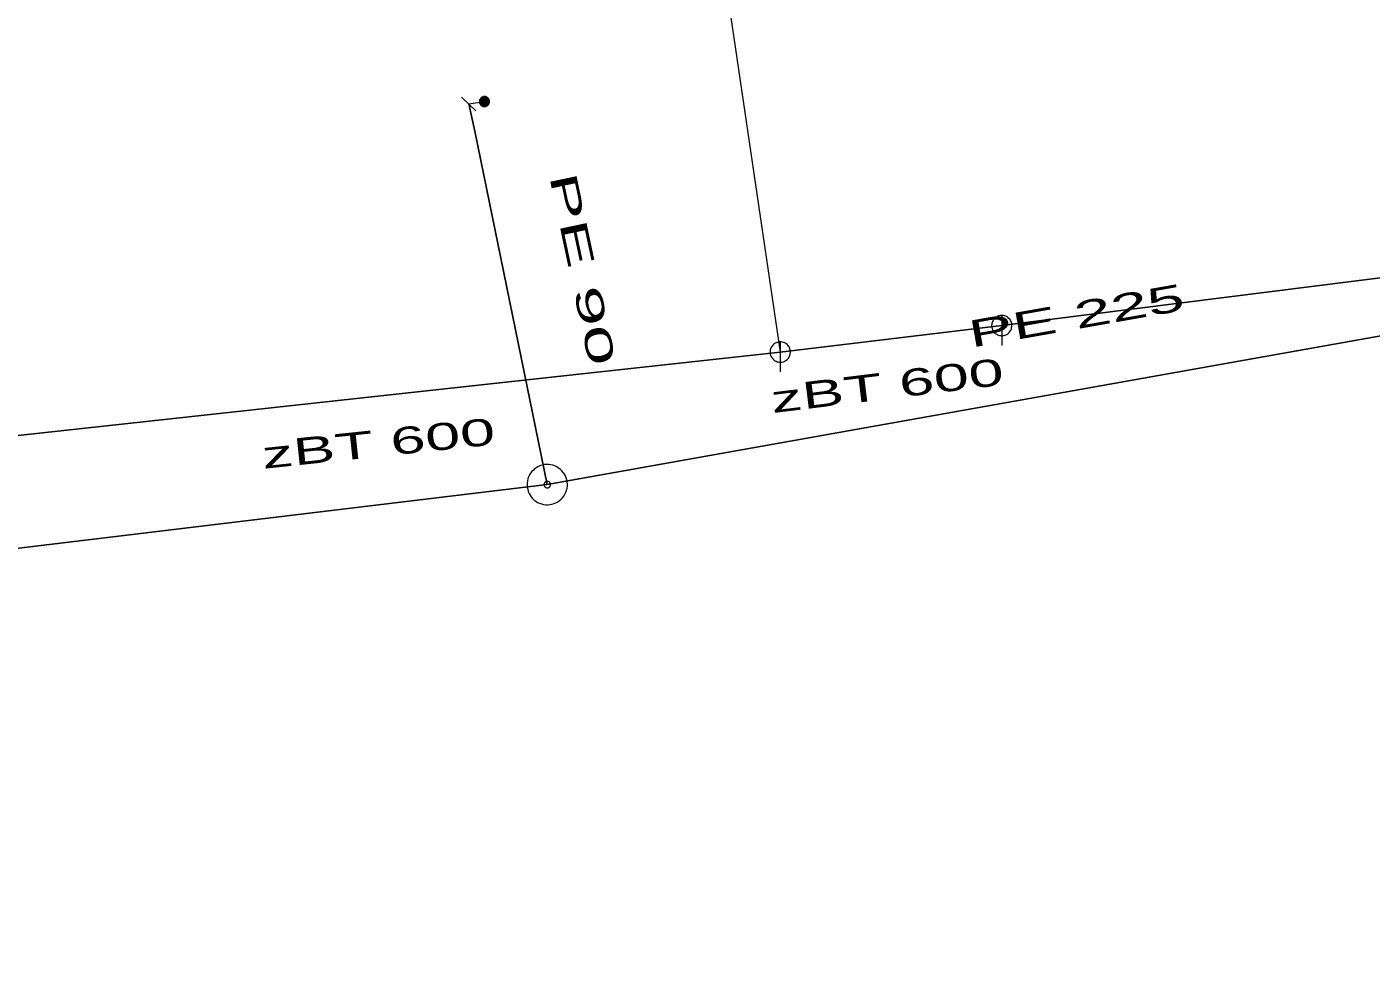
# Model space of a CAD drawing. Extents: x -687468 to -685917, y -974192 to -973456.
# Drawn here: x -686636.37 to -686603.02, y -973637.07 to -973613.79 of the extents above; entities that cross this region are included whole.
import ezdxf
from ezdxf.enums import TextEntityAlignment as Align

# ---------------------------------------------------------------- set-up
doc = ezdxf.new("R2010")
doc.units = 0
doc.header["$LTSCALE"] = 0.27
for name, color, linetype, lineweight in [('1', 7, 'Continuous', 13), ('11', 7, 'Continuous', 13), ('14', 7, 'Continuous', 25), ('17', 7, 'Continuous', 25), ('22', 7, 'Continuous', 13), ('34', 7, 'Continuous', 13), ('47', 7, 'Continuous', 13), ('9', 7, 'Continuous', 13)]:
    doc.layers.add(name, color=color, linetype=linetype, lineweight=lineweight)

msp = doc.modelspace()

# ---------------------------------------------------------------- linework, layer by layer
at = {"layer": '11'}
msp.add_lwpolyline([(-686607.101, -973609.27), (-686619.328, -973610.691), (-686617.682, -973621.851)], dxfattribs=at)
at = {"layer": '14', "lineweight": 13}
msp.add_line((-686625.41, -973615.7), (-686625.019, -973615.64), dxfattribs=at)
at = {"layer": '14'}
for p, q in [((-686587.336, -973618.056), (-686612.187, -973621.194)), ((-686612.187, -973621.194), (-686617.682, -973621.851)), ((-686617.682, -973621.851), (-686637.412, -973624.013))]:
    msp.add_line(p, q, dxfattribs=at)
at = {"layer": '17'}
for p, q in [((-686596.546, -973620.333), (-686623.461, -973625.138)), ((-686623.461, -973625.138), (-686722.815, -973637.075))]:
    msp.add_line(p, q, dxfattribs=at)
msp.add_lwpolyline([(-686623.461, -973625.138), (-686625.255, -973616.375), (-686625.41, -973615.7)], dxfattribs=at)
at = {"layer": '22'}
for p, q in [((-686612.186, -973620.942), (-686612.187, -973621.686)), ((-686617.681, -973621.599), (-686617.682, -973622.343))]:
    msp.add_line(p, q, dxfattribs=at)
for points in [[(-686611.935, -973621.194), (-686611.936, -973621.168), (-686611.94, -973621.142), (-686611.946, -973621.116), (-686611.956, -973621.092), (-686611.968, -973621.068), (-686611.982, -973621.046), (-686611.999, -973621.025), (-686612.017, -973621.007), (-686612.038, -973620.99), (-686612.06, -973620.976), (-686612.084, -973620.964), (-686612.108, -973620.954), (-686612.134, -973620.948), (-686612.16, -973620.944), (-686612.186, -973620.942), (-686612.212, -973620.943), (-686612.238, -973620.947), (-686612.264, -973620.953), (-686612.289, -973620.963), (-686612.312, -973620.975), (-686612.334, -973620.989), (-686612.355, -973621.006), (-686612.373, -973621.024), (-686612.39, -973621.045), (-686612.404, -973621.067), (-686612.416, -973621.091), (-686612.426, -973621.115), (-686612.433, -973621.141), (-686612.437, -973621.167), (-686612.439, -973621.193), (-686612.438, -973621.219), (-686612.434, -973621.245), (-686612.427, -973621.271), (-686612.417, -973621.296), (-686612.405, -973621.319), (-686612.391, -973621.341), (-686612.374, -973621.362), (-686612.356, -973621.38), (-686612.335, -973621.397), (-686612.313, -973621.411), (-686612.29, -973621.423), (-686612.265, -973621.433), (-686612.239, -973621.44), (-686612.213, -973621.444), (-686612.187, -973621.446), (-686612.161, -973621.445), (-686612.135, -973621.441), (-686612.109, -973621.434), (-686612.085, -973621.424), (-686612.061, -973621.412), (-686612.039, -973621.398), (-686612.018, -973621.381), (-686612, -973621.363), (-686611.983, -973621.342), (-686611.969, -973621.32), (-686611.957, -973621.297), (-686611.947, -973621.272), (-686611.941, -973621.246), (-686611.937, -973621.22)], [(-686617.43, -973621.851), (-686617.431, -973621.825), (-686617.435, -973621.799), (-686617.441, -973621.773), (-686617.451, -973621.749), (-686617.463, -973621.725), (-686617.477, -973621.703), (-686617.494, -973621.682), (-686617.512, -973621.664), (-686617.533, -973621.647), (-686617.555, -973621.633), (-686617.579, -973621.621), (-686617.603, -973621.611), (-686617.629, -973621.605), (-686617.655, -973621.601), (-686617.681, -973621.599), (-686617.707, -973621.6), (-686617.733, -973621.604), (-686617.759, -973621.61), (-686617.784, -973621.62), (-686617.807, -973621.632), (-686617.829, -973621.646), (-686617.85, -973621.663), (-686617.868, -973621.681), (-686617.885, -973621.702), (-686617.899, -973621.724), (-686617.911, -973621.748), (-686617.921, -973621.772), (-686617.928, -973621.798), (-686617.932, -973621.824), (-686617.934, -973621.85), (-686617.933, -973621.876), (-686617.929, -973621.902), (-686617.922, -973621.928), (-686617.912, -973621.953), (-686617.9, -973621.976), (-686617.886, -973621.998), (-686617.869, -973622.019), (-686617.851, -973622.037), (-686617.83, -973622.054), (-686617.808, -973622.068), (-686617.785, -973622.08), (-686617.76, -973622.09), (-686617.734, -973622.097), (-686617.708, -973622.101), (-686617.682, -973622.103), (-686617.656, -973622.102), (-686617.63, -973622.098), (-686617.604, -973622.091), (-686617.58, -973622.081), (-686617.556, -973622.069), (-686617.534, -973622.055), (-686617.513, -973622.038), (-686617.495, -973622.02), (-686617.478, -973621.999), (-686617.464, -973621.977), (-686617.452, -973621.954), (-686617.442, -973621.929), (-686617.436, -973621.903), (-686617.432, -973621.877)]]:
    msp.add_lwpolyline(points, close=True, dxfattribs=at)
at = {"layer": '34'}
msp.add_line((-686625.589, -973615.528), (-686625.23, -973615.871), dxfattribs=at)
at = {"layer": '47'}
for points in [[(-686622.965, -973625.072), (-686622.975, -973625.021), (-686622.989, -973624.97), (-686623.01, -973624.922), (-686623.034, -973624.876), (-686623.064, -973624.833), (-686623.099, -973624.793), (-686623.137, -973624.758), (-686623.178, -973624.726), (-686623.222, -973624.698), (-686623.27, -973624.675), (-686623.319, -973624.658), (-686623.37, -973624.646), (-686623.422, -973624.639), (-686623.474, -973624.638), (-686623.526, -973624.642), (-686623.577, -973624.652), (-686623.628, -973624.666), (-686623.677, -973624.687), (-686623.722, -973624.711), (-686623.765, -973624.741), (-686623.805, -973624.776), (-686623.841, -973624.814), (-686623.873, -973624.855), (-686623.901, -973624.899), (-686623.923, -973624.947), (-686623.94, -973624.996), (-686623.953, -973625.047), (-686623.959, -973625.099), (-686623.96, -973625.151), (-686623.956, -973625.203), (-686623.946, -973625.254), (-686623.932, -973625.305), (-686623.912, -973625.354), (-686623.887, -973625.399), (-686623.857, -973625.442), (-686623.823, -973625.482), (-686623.785, -973625.519), (-686623.744, -973625.55), (-686623.699, -973625.578), (-686623.651, -973625.6), (-686623.602, -973625.617), (-686623.552, -973625.63), (-686623.499, -973625.636), (-686623.447, -973625.637), (-686623.395, -973625.633), (-686623.344, -973625.623), (-686623.293, -973625.609), (-686623.245, -973625.589), (-686623.199, -973625.564), (-686623.156, -973625.534), (-686623.116, -973625.5), (-686623.08, -973625.462), (-686623.049, -973625.421), (-686623.021, -973625.376), (-686622.998, -973625.328), (-686622.981, -973625.279), (-686622.969, -973625.229), (-686622.962, -973625.176), (-686622.961, -973625.124)], [(-686623.379, -973625.127), (-686623.38, -973625.118), (-686623.383, -973625.11), (-686623.386, -973625.102), (-686623.39, -973625.095), (-686623.396, -973625.088), (-686623.401, -973625.081), (-686623.407, -973625.075), (-686623.414, -973625.07), (-686623.422, -973625.066), (-686623.429, -973625.062), (-686623.438, -973625.059), (-686623.446, -973625.057), (-686623.454, -973625.056), (-686623.462, -973625.055), (-686623.471, -973625.056), (-686623.48, -973625.057), (-686623.488, -973625.06), (-686623.496, -973625.063), (-686623.503, -973625.067), (-686623.51, -973625.073), (-686623.517, -973625.078), (-686623.523, -973625.084), (-686623.528, -973625.091), (-686623.533, -973625.099), (-686623.536, -973625.106), (-686623.539, -973625.115), (-686623.541, -973625.123), (-686623.542, -973625.131), (-686623.543, -973625.139), (-686623.542, -973625.148), (-686623.541, -973625.157), (-686623.538, -973625.165), (-686623.535, -973625.173), (-686623.531, -973625.18), (-686623.525, -973625.187), (-686623.521, -973625.194), (-686623.514, -973625.2), (-686623.507, -973625.205), (-686623.499, -973625.21), (-686623.492, -973625.213), (-686623.483, -973625.216), (-686623.475, -973625.218), (-686623.467, -973625.219), (-686623.459, -973625.22), (-686623.45, -973625.219), (-686623.441, -973625.218), (-686623.433, -973625.215), (-686623.425, -973625.212), (-686623.418, -973625.208), (-686623.411, -973625.202), (-686623.404, -973625.198), (-686623.398, -973625.191), (-686623.393, -973625.184), (-686623.389, -973625.176), (-686623.385, -973625.169), (-686623.382, -973625.16), (-686623.38, -973625.152), (-686623.379, -973625.144), (-686623.378, -973625.136)]]:
    msp.add_lwpolyline(points, close=True, dxfattribs=at)
at = {"layer": '9'}
for points in [[(-686624.892, -973615.64), (-686624.894, -973615.627), (-686624.896, -973615.614), (-686624.899, -973615.601), (-686624.904, -973615.589), (-686624.909, -973615.577), (-686624.917, -973615.566), (-686624.924, -973615.556), (-686624.934, -973615.546), (-686624.945, -973615.538), (-686624.956, -973615.531), (-686624.968, -973615.525), (-686624.98, -973615.52), (-686624.993, -973615.517), (-686625.005, -973615.515), (-686625.019, -973615.514), (-686625.032, -973615.515), (-686625.044, -973615.517), (-686625.058, -973615.52), (-686625.07, -973615.525), (-686625.081, -973615.531), (-686625.093, -973615.538), (-686625.103, -973615.546), (-686625.113, -973615.556), (-686625.12, -973615.566), (-686625.128, -973615.577), (-686625.134, -973615.589), (-686625.139, -973615.601), (-686625.142, -973615.614), (-686625.144, -973615.627), (-686625.145, -973615.64), (-686625.144, -973615.653), (-686625.142, -973615.666), (-686625.139, -973615.679), (-686625.134, -973615.691), (-686625.128, -973615.703), (-686625.12, -973615.714), (-686625.113, -973615.724), (-686625.103, -973615.734), (-686625.093, -973615.742), (-686625.081, -973615.749), (-686625.07, -973615.755), (-686625.058, -973615.76), (-686625.044, -973615.763), (-686625.032, -973615.765), (-686625.019, -973615.766), (-686625.005, -973615.765), (-686624.993, -973615.763), (-686624.98, -973615.76), (-686624.968, -973615.755), (-686624.956, -973615.749), (-686624.945, -973615.742), (-686624.934, -973615.734), (-686624.924, -973615.724), (-686624.917, -973615.714), (-686624.909, -973615.703), (-686624.904, -973615.691), (-686624.899, -973615.679), (-686624.896, -973615.666), (-686624.894, -973615.653)], [(-686624.913, -973615.64), (-686624.913, -973615.629), (-686624.914, -973615.618), (-686624.918, -973615.607), (-686624.922, -973615.597), (-686624.927, -973615.587), (-686624.933, -973615.578), (-686624.94, -973615.569), (-686624.948, -973615.561), (-686624.956, -973615.554), (-686624.966, -973615.548), (-686624.976, -973615.543), (-686624.985, -973615.539), (-686624.997, -973615.536), (-686625.007, -973615.534), (-686625.019, -973615.534), (-686625.03, -973615.534), (-686625.041, -973615.536), (-686625.052, -973615.539), (-686625.061, -973615.543), (-686625.071, -973615.548), (-686625.081, -973615.554), (-686625.09, -973615.561), (-686625.098, -973615.569), (-686625.105, -973615.578), (-686625.11, -973615.587), (-686625.115, -973615.597), (-686625.12, -973615.607), (-686625.123, -973615.618), (-686625.125, -973615.629), (-686625.125, -973615.64), (-686625.125, -973615.651), (-686625.123, -973615.662), (-686625.12, -973615.673), (-686625.115, -973615.683), (-686625.11, -973615.693), (-686625.105, -973615.702), (-686625.098, -973615.711), (-686625.09, -973615.719), (-686625.081, -973615.726), (-686625.071, -973615.732), (-686625.061, -973615.737), (-686625.052, -973615.741), (-686625.041, -973615.744), (-686625.03, -973615.746), (-686625.019, -973615.746), (-686625.007, -973615.746), (-686624.997, -973615.744), (-686624.985, -973615.741), (-686624.976, -973615.737), (-686624.966, -973615.732), (-686624.956, -973615.726), (-686624.948, -973615.719), (-686624.94, -973615.711), (-686624.933, -973615.702), (-686624.927, -973615.693), (-686624.922, -973615.683), (-686624.918, -973615.673), (-686624.914, -973615.662), (-686624.913, -973615.651)], [(-686624.931, -973615.64), (-686624.933, -973615.631), (-686624.934, -973615.622), (-686624.936, -973615.613), (-686624.94, -973615.605), (-686624.944, -973615.597), (-686624.949, -973615.589), (-686624.955, -973615.582), (-686624.961, -973615.576), (-686624.968, -973615.57), (-686624.976, -973615.565), (-686624.983, -973615.561), (-686624.992, -973615.558), (-686625, -973615.555), (-686625.01, -973615.554), (-686625.019, -973615.553), (-686625.027, -973615.554), (-686625.037, -973615.555), (-686625.046, -973615.558), (-686625.054, -973615.561), (-686625.061, -973615.565), (-686625.07, -973615.57), (-686625.076, -973615.576), (-686625.083, -973615.582), (-686625.088, -973615.589), (-686625.093, -973615.597), (-686625.098, -973615.605), (-686625.101, -973615.613), (-686625.103, -973615.622), (-686625.105, -973615.631), (-686625.106, -973615.64), (-686625.105, -973615.649), (-686625.103, -973615.658), (-686625.101, -973615.667), (-686625.098, -973615.675), (-686625.093, -973615.683), (-686625.088, -973615.691), (-686625.083, -973615.698), (-686625.076, -973615.704), (-686625.07, -973615.71), (-686625.061, -973615.715), (-686625.054, -973615.719), (-686625.046, -973615.722), (-686625.037, -973615.725), (-686625.027, -973615.726), (-686625.019, -973615.727), (-686625.01, -973615.726), (-686625, -973615.725), (-686624.992, -973615.722), (-686624.983, -973615.719), (-686624.976, -973615.715), (-686624.968, -973615.71), (-686624.961, -973615.704), (-686624.955, -973615.698), (-686624.949, -973615.691), (-686624.944, -973615.683), (-686624.94, -973615.675), (-686624.936, -973615.667), (-686624.934, -973615.658), (-686624.933, -973615.649)], [(-686624.951, -973615.64), (-686624.951, -973615.633), (-686624.954, -973615.626), (-686624.955, -973615.619), (-686624.958, -973615.613), (-686624.961, -973615.607), (-686624.965, -973615.601), (-686624.968, -973615.595), (-686624.973, -973615.59), (-686624.98, -973615.586), (-686624.985, -973615.582), (-686624.992, -973615.579), (-686624.998, -973615.576), (-686625.005, -973615.575), (-686625.012, -973615.573), (-686625.019, -973615.573), (-686625.026, -973615.573), (-686625.032, -973615.575), (-686625.039, -973615.576), (-686625.046, -973615.579), (-686625.053, -973615.582), (-686625.058, -973615.586), (-686625.064, -973615.59), (-686625.069, -973615.595), (-686625.073, -973615.601), (-686625.076, -973615.607), (-686625.08, -973615.613), (-686625.083, -973615.619), (-686625.085, -973615.626), (-686625.086, -973615.633), (-686625.086, -973615.64), (-686625.086, -973615.647), (-686625.085, -973615.654), (-686625.083, -973615.661), (-686625.08, -973615.667), (-686625.076, -973615.674), (-686625.073, -973615.679), (-686625.069, -973615.685), (-686625.064, -973615.69), (-686625.058, -973615.694), (-686625.053, -973615.698), (-686625.046, -973615.701), (-686625.039, -973615.704), (-686625.032, -973615.706), (-686625.026, -973615.707), (-686625.019, -973615.707), (-686625.012, -973615.707), (-686625.005, -973615.706), (-686624.998, -973615.704), (-686624.992, -973615.701), (-686624.985, -973615.698), (-686624.98, -973615.694), (-686624.973, -973615.69), (-686624.968, -973615.685), (-686624.965, -973615.679), (-686624.961, -973615.674), (-686624.958, -973615.667), (-686624.955, -973615.661), (-686624.954, -973615.654), (-686624.951, -973615.647)], [(-686624.972, -973615.64), (-686624.972, -973615.635), (-686624.973, -973615.63), (-686624.973, -973615.625), (-686624.976, -973615.621), (-686624.978, -973615.616), (-686624.981, -973615.612), (-686624.983, -973615.609), (-686624.988, -973615.605), (-686624.99, -973615.602), (-686624.995, -973615.599), (-686625, -973615.597), (-686625.004, -973615.595), (-686625.009, -973615.594), (-686625.014, -973615.593), (-686625.019, -973615.593), (-686625.024, -973615.593), (-686625.029, -973615.594), (-686625.034, -973615.595), (-686625.038, -973615.597), (-686625.043, -973615.599), (-686625.047, -973615.602), (-686625.051, -973615.605), (-686625.054, -973615.609), (-686625.056, -973615.612), (-686625.059, -973615.616), (-686625.061, -973615.621), (-686625.064, -973615.625), (-686625.065, -973615.63), (-686625.066, -973615.635), (-686625.066, -973615.64), (-686625.066, -973615.645), (-686625.065, -973615.65), (-686625.064, -973615.655), (-686625.061, -973615.659), (-686625.059, -973615.664), (-686625.056, -973615.668), (-686625.054, -973615.672), (-686625.051, -973615.675), (-686625.047, -973615.678), (-686625.043, -973615.681), (-686625.038, -973615.683), (-686625.034, -973615.685), (-686625.029, -973615.686), (-686625.024, -973615.687), (-686625.019, -973615.687), (-686625.014, -973615.687), (-686625.009, -973615.686), (-686625.004, -973615.685), (-686625, -973615.683), (-686624.995, -973615.681), (-686624.99, -973615.678), (-686624.988, -973615.675), (-686624.983, -973615.672), (-686624.981, -973615.668), (-686624.978, -973615.664), (-686624.976, -973615.659), (-686624.973, -973615.655), (-686624.973, -973615.65), (-686624.972, -973615.645)], [(-686624.992, -973615.64), (-686624.992, -973615.637), (-686624.992, -973615.634), (-686624.993, -973615.632), (-686624.994, -973615.629), (-686624.995, -973615.626), (-686624.997, -973615.624), (-686624.999, -973615.622), (-686625, -973615.62), (-686625.003, -973615.618), (-686625.005, -973615.616), (-686625.007, -973615.615), (-686625.011, -973615.614), (-686625.012, -973615.613), (-686625.016, -973615.613), (-686625.019, -973615.613), (-686625.022, -973615.613), (-686625.025, -973615.613), (-686625.027, -973615.614), (-686625.03, -973615.615), (-686625.032, -973615.616), (-686625.034, -973615.618), (-686625.038, -973615.62), (-686625.039, -973615.622), (-686625.041, -973615.624), (-686625.043, -973615.626), (-686625.044, -973615.629), (-686625.044, -973615.632), (-686625.046, -973615.634), (-686625.046, -973615.637), (-686625.047, -973615.64), (-686625.046, -973615.643), (-686625.046, -973615.646), (-686625.044, -973615.649), (-686625.044, -973615.651), (-686625.043, -973615.654), (-686625.041, -973615.656), (-686625.039, -973615.659), (-686625.038, -973615.661), (-686625.034, -973615.662), (-686625.032, -973615.664), (-686625.03, -973615.665), (-686625.027, -973615.666), (-686625.025, -973615.667), (-686625.022, -973615.667), (-686625.019, -973615.668), (-686625.016, -973615.667), (-686625.012, -973615.667), (-686625.011, -973615.666), (-686625.007, -973615.665), (-686625.005, -973615.664), (-686625.003, -973615.662), (-686625, -973615.661), (-686624.999, -973615.659), (-686624.997, -973615.656), (-686624.995, -973615.654), (-686624.994, -973615.651), (-686624.993, -973615.649), (-686624.992, -973615.646), (-686624.992, -973615.643)], [(-686625.011, -973615.64), (-686625.011, -973615.639), (-686625.011, -973615.638), (-686625.012, -973615.638), (-686625.012, -973615.637), (-686625.012, -973615.636), (-686625.012, -973615.635), (-686625.012, -973615.635), (-686625.014, -973615.634), (-686625.014, -973615.634), (-686625.015, -973615.633), (-686625.016, -973615.633), (-686625.017, -973615.633), (-686625.017, -973615.632), (-686625.017, -973615.632), (-686625.019, -973615.632), (-686625.02, -973615.632), (-686625.021, -973615.632), (-686625.021, -973615.633), (-686625.022, -973615.633), (-686625.022, -973615.633), (-686625.024, -973615.634), (-686625.024, -973615.634), (-686625.025, -973615.635), (-686625.025, -973615.635), (-686625.026, -973615.636), (-686625.026, -973615.637), (-686625.027, -973615.638), (-686625.027, -973615.638), (-686625.027, -973615.639), (-686625.027, -973615.64), (-686625.027, -973615.641), (-686625.027, -973615.642), (-686625.027, -973615.642), (-686625.026, -973615.643), (-686625.026, -973615.644), (-686625.025, -973615.645), (-686625.025, -973615.645), (-686625.024, -973615.646), (-686625.024, -973615.646), (-686625.022, -973615.647), (-686625.022, -973615.647), (-686625.021, -973615.648), (-686625.021, -973615.648), (-686625.02, -973615.648), (-686625.019, -973615.648), (-686625.017, -973615.648), (-686625.017, -973615.648), (-686625.017, -973615.648), (-686625.016, -973615.647), (-686625.015, -973615.647), (-686625.014, -973615.646), (-686625.014, -973615.646), (-686625.012, -973615.645), (-686625.012, -973615.645), (-686625.012, -973615.644), (-686625.012, -973615.643), (-686625.012, -973615.642), (-686625.011, -973615.642), (-686625.011, -973615.641)]]:
    msp.add_lwpolyline(points, close=True, dxfattribs=at)

# ---------------------------------------------------------------- texts
at = {"layer": '1'}
for s, rotation, width, p in [('PE 90 ', 282, 2, (-686622.86, -973620.103)), ('PE 225', 10, 1.85, (-686610.28, -973621.275)), ('zBT 600 ', 7, 1.75, (-686614.776, -973622.985)), ('zBT 600 ', 6, 1.75, (-686627.4, -973624.42))]:
    msp.add_text(s, height=0.6667, rotation=rotation, dxfattribs=dict(at, width=width)).set_placement(p, align=Align.CENTER)

doc.saveas('drawing.dxf')
